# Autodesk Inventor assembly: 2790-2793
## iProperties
Author: Administrator
Created: 2002-03
Part Number: 2790-2793
Document SubType Name: Assembly
Designer: Administrator
Control State: 0
Master: False
Checked Out: False
PropertySet Name: Design Tracking Control
Shininess: 64.0
Angle Display Precision: 2
Document Length Units: 11272
Document Angle Units: 11286
Document Time Units: 11279
Document Mass Units: 11290
Document Length Units Precision: 3
Document Angle Units Precision: 2
Compacted: False
PropertySet Name: _Private Model Information
Density: 0.0
Volumn: 0.0
Area: 0.0
PropertySet Name: Model Information
